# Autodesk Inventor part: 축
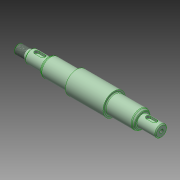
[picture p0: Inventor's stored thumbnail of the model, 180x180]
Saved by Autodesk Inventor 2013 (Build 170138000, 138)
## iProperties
Created: 2024-02
Part Number: 축
Material: 강철, 탄소
Document SubType Name: Modeling
Designer: mdu-01
Density: 1 g/cm^3
Author: mdu-01
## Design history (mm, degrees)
sketch "스케치1"
  geometry: L1 (0, 0)-(160, 0); L2 (0, 0)-(0, -5); L3 (0, -5)-(14, -5); L4 (14, -5)-(14, -6); L5 (15, -7)-(33, -7); L6 (33, -7)-(33, -7.923); L7 (36.134, -10)-(64, -10); L8 (65, -11)-(65, -12.5); L9 (65, -12.5)-(107, -12.5); L10 (107, -12.5)-(107, -11); L11 (108, -10)-(135.866, -10); L12 (139, -7.923)-(139, -6.5); L13 (139, -6.5)-(159, -6.5); L14 (160, -5.5)-(160, 0); L15 (159, -6.5)-(160, -5.5); L16 (14, -6)-(15, -7); L17 (33.5, -8.789)-(35.134, -9.732); L18 (138.5, -8.789)-(136.866, -9.732); L19 (18, 7)-(30, 7); L20 (30, 7)-(30, 4); L21 (30, 4)-(18, 4); L22 (18, 4)-(18, 7); L23 (143, 6.5)-(155, 6.5); L24 (155, 6.5)-(155, 3.5); L25 (155, 3.5)-(143, 3.5); L26 (143, 3.5)-(143, 6.5); A1 r 1 centre (64, -11) between (65, -11) and (64, -10); A2 r 1 centre (108, -11) between (108, -10) and (107, -11); A3 r 1 centre (34, -7.923) between (33, -7.923) and (33.5, -8.789); A4 r 1 centre (138, -7.923) between (138.5, -8.789) and (139, -7.923); A5 r 2 centre (135.866, -8) between (135.866, -10) and (136.866, -9.732); A6 r 2 centre (36.134, -8) between (35.134, -9.732) and (36.134, -10); 4 further points
  constraints: 52 end point, 15 parallel, 12 point on circle, 12 tangent, 8 point on line, 6 centre point, 4 perpendicular, 3 equal radius, 3 horizontal, 1 collinear
  dimensions: "d0" = 160 distance of L1.start L1.end; "d1" = 14 distance between parallel lines of L4 L2; "d2" = 33 distance between parallel lines of L6 L2; "d3" = 65 distance between parallel lines of L8 L2; "d4" = 21 distance between parallel lines of L12 L14; "d5" = 53 distance between parallel lines of L10 L14; "d6" = 10 diameter of L3 L1; "d7" = 14 diameter of L5 L1; "d8" = 20 diameter of L7 L1; "d9" = 13 diameter of L13 L1; "d10" = 25 diameter of L9 L1; "d11" = 1 radius of A1; "d12" = 1 distance of L13.end point (160, -6.5); "d13" = 1 distance of L14.start point (160, -6.5) (= d12); "d14" = 1 distance of L4.end point (14, -7) (= d12); "d15" = 1 distance of L5.start point (14, -7) (= d14); "d16" = 17 diameter of point (139, -8.5) L1; "d17" = 30 deg angle of L11 L18; "d18" = 17 diameter of point (33, -8.5) L1; "d19" = 30 deg angle of L7 L17; "d20" = 1 radius of A3; "d21" = 2 radius of A5; "d22" = 3 distance between parallel lines of L21 L19; "d23" = 12 distance between parallel lines of L20 L22; "d24" = 3 distance between parallel lines of L20 L6; "d25" = 14 diameter of L19 L1; "d26" = 3 distance between parallel lines of L25 L23; "d27" = 12 distance between parallel lines of L24 L26; "d28" = 4 distance between parallel lines of L26 L12; "d29" = 13 diameter of L23 L1
revolve "회전1" stored, may be unused: angle "d30" = 90 deg
extrude "돌출1" cut sketch "스케치1" stored distance "d31" = 5; taper "d32" = 0 deg
fillet "모깎기1" dims "d33" = 2.5
feature "스레드1" dims "d34" = 11, "d35" = 0
chamfer "모따기1" distance "d36" = 0.541; stored, may be unused: second distance "d37" = 2, angle "d38" = 45 deg
hole "구멍1" diameter "d41" = 4.134; stored, may be unused: countersink angle "d45" = 90 deg, drill point angle "d47" = 118 deg; dims "d39" = 10, "d40" = 10, "d42" = 10, "d43" = 4, "d44" = 2, "d46" = 12
node "솔리드1"
